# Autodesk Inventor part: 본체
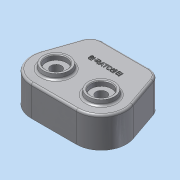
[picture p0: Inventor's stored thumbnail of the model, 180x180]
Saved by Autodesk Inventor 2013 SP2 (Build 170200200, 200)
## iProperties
Created: 2014-12
Part Number: 본체
Material: 알루미늄 6061
Document SubType Name: Modeling
Designer: dgall
Density: 2.71 g/cm^3
Mass: 613.441 g
Surface Area: 665.08 cm^2
Volume: 226.362 cm^3
Author: dgall
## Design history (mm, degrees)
sketch "스케치1"
  geometry: L1 (-47, 36)-(47, 36); L2 (47, 36)-(66.565, -20.803); L3 (32.527, -68.527)-(-32.527, -68.527); L4 (-66.565, -20.803)-(-47, 36); L5 (0, 0)-(-56.889, -56.889); L6 (0, 0)-(56.889, -56.889); L7 (0, 0)-(0, -80.453); L8 (61.837, -22.432)-(43.434, 31); L9 (43.434, 31)-(-43.434, 31); L10 (-43.434, 31)-(-61.837, -22.432); L11 (-32.527, -63.527)-(32.527, -63.527); C1 r 24 at (0, 0); C2 r 24 at (-32.527, -32.527); C3 r 24 at (32.527, -32.527); A1 r 36 centre (-32.527, -32.527) between (-66.565, -20.803) and (-32.527, -68.527); A2 r 36 centre (32.527, -32.527) between (32.527, -68.527) and (66.565, -20.803); A3 r 31 centre (-32.527, -32.527) between (-61.837, -22.432) and (-32.527, -63.527); A4 r 31 centre (32.527, -32.527) between (32.527, -63.527) and (61.837, -22.432); A5 r 46 centre (0, 0) between (-32.527, -32.527) and (32.527, -32.527); 2 further points
  constraints: 22 end point, 10 point on circle, 8 centre point, 4 coincident, 3 equal radius, 3 tangent, 2 equal length, 2 parallel, 2 point on line, 1 horizontal, 1 midpoint, 1 perpendicular, 1 vertical alignment, 5 other
  dimensions: "d2" = 48 diameter of C1; "d4" = 36 distance from line of L5.start L1; "d5" = 94 distance of L1.start L1.end; "d6" = 90 deg angle of L5 L6; "d7" = 45 deg angle of L7 L6; "d13" = 36 radius of A1; "d14" = 5 distance between parallel lines of L10 L4; "d26" = 46 radius of A5
extrude "돌출1" new body sketch "스케치1" distance "d15" = 44; taper "d16" = 0 deg
extrude "돌출2" cut sketch "스케치1" distance "d17" = 34; taper "d18" = 0 deg
sketch "스케치2"
  geometry: C1 r 24 at (0, 0); C2 r 24 at (-32.527, -32.527); C3 r 24 at (32.527, -32.527); A1 r 31 centre (-32.527, -32.527) between (-61.837, -22.432) and (-32.527, -63.527) reference; A2 r 31 centre (32.527, -32.527) between (32.527, -63.527) and (61.837, -22.432) reference; 1 further point
  constraints: 3 centre point, 3 coincident, 2 equal radius
  dimensions: "d19" = 48 diameter of C1
extrude "돌출3" join sketch "스케치2" distance "d21" = 11; taper "d22" = 0 deg
sketch "스케치3"
  geometry: C1 r 24 at (0, 0) reference; C2 r 20 at (0, 0); C3 r 10 at (0, 0)
  constraints: 2 centre point
  dimensions: "d23" = 40 diameter of C2; "d25" = 20 diameter of C3
extrude "돌출4" cut sketch "스케치3" distance "d27" = 12; taper "d28" = 0 deg
extrude "돌출5" cut sketch "스케치3" distance "d29" = 15; taper "d30" = 0 deg
sketch "스케치4"
  geometry: C1 r 20 at (-32.527, -32.527); C2 r 20 at (32.527, -32.527); A1 r 36 centre (-32.527, -32.527) between (-66.565, -20.803) and (-32.527, -68.527) reference; A2 r 36 centre (32.527, -32.527) between (32.527, -68.527) and (66.565, -20.803) reference; 1 further point
  constraints: 2 centre point, 2 coincident, 1 equal radius
  dimensions: "d31" = 40 diameter of C1
extrude "돌출6" join sketch "스케치4" distance "d33" = 7; taper "d34" = -10 deg
node "작업 평면1"
sketch "스케치5"
  geometry: L1 (-18.766, 51)-(18.766, 51) reference; L2 (-24, 23)-(24, 23) reference; L3 (41.054, 23)-(89.054, 23) reference; L4 (46.288, 51)-(83.82, 51) reference; L5 (0, 51)-(0, 23); L6 (65.054, 51)-(65.054, 23); L7 (0, 51)-(-15, 51); L8 (-15, 51)-(-15, 44); L9 (-15, 44)-(-7.75, 44); L10 (-7.75, 44)-(-7.75, 34); L11 (-7.75, 34)-(-17.5, 34); L12 (-17.5, 34)-(-17.5, 23); L13 (-17.5, 23)-(0, 23); L14 (65.054, 51)-(50.054, 51); L15 (50.054, 51)-(50.054, 44); L16 (50.054, 44)-(57.304, 44); L17 (57.304, 44)-(57.304, 34); L18 (57.304, 34)-(47.554, 34); L19 (47.554, 34)-(47.554, 23); L20 (47.554, 23)-(65.054, 23); 5 further points
  constraints: 32 end point, 7 perpendicular, 4 midpoint, 4 point on line, 3 parallel, 1 collinear, 1 horizontal
  dimensions: "d36" = 7 distance of L7.end L8.end; "d38" = 10 distance of L9.end L10.end; "d39" = 30 diameter of L8 L5; "d40" = 15.5 diameter of L10 L5; "d41" = 35 diameter of L12 L5; "d42" = 7 distance of L14.end L15.end; "d43" = 10 distance of L16.end L17.end; "d44" = 30 diameter of L15 L6; "d45" = 15.5 diameter of L17 L6; "d46" = 35 diameter of L19 L6
revolve "회전1" stored, may be unused: angle "d47" = 90 deg
revolve "회전2" stored, may be unused: angle "d48" = 90 deg
fillet "모깎기1" dims "d49" = 18
sketch "스케치6"
  geometry: L1 (34.162, 36)-(-34.162, 36) reference; L2 (-61.837, -22.432)-(-43.434, 31) reference; L3 (43.434, 31)-(61.837, -22.432) reference; L4 (32.527, -63.527)-(-32.527, -63.527) reference; A1 r 8 centre (-51.7, 7) between (-54.305, -0.564) and (-49.095, 14.564); A2 r 8 centre (51.7, 7) between (49.095, 14.564) and (54.305, -0.564); A3 r 8 centre (0, -63.527) between (8, -63.527) and (-8, -63.527); 1 further point
  constraints: 8 point on line, 6 point on circle, 3 centre point, 2 equal radius, 1 midpoint
  dimensions: "d50" = 8 radius of A1; "d52" = 29 distance from line of A1.centre L1; "d53" = 29 distance from line of A2.centre L1
extrude "돌출7" join sketch "스케치6" stored distance "d54" = 7; taper "d55" = 0 deg
fillet "모깎기2" dims "d56" = 13
fillet "모깎기3" dims "d57" = 3
hole "구멍1" diameter "d60" = 4.134; stored, may be unused: countersink angle "d64" = 90 deg, drill point angle "d66" = 118 deg; dims "d58" = 10, "d59" = 10, "d61" = 20, "d62" = 4, "d63" = 2, "d65" = 23
hole "구멍2" diameter "d69" = 4.134; stored, may be unused: countersink angle "d73" = 90 deg, drill point angle "d75" = 118 deg; dims "d67" = 10, "d68" = 10, "d70" = 20, "d71" = 4, "d72" = 2, "d74" = 23
hole "구멍3" diameter "d78" = 4.134; stored, may be unused: countersink angle "d82" = 90 deg, drill point angle "d84" = 118 deg; dims "d76" = 10, "d77" = 10, "d79" = 20, "d80" = 4, "d81" = 2, "d83" = 23
fillet "모깎기4" dims "d85" = 3
fillet "모깎기5" dims "d86" = 3
fillet "모깎기6" dims "d87" = 3
fillet "모깎기7" dims "d88" = 0.3
chamfer "모따기1" distance "d89" = 1; stored, may be unused: second distance "d90" = 2, angle "d91" = 45 deg
fillet "모깎기8" dims "d92" = 0.1
fillet "모깎기9" dims "d93" = 3
sketch "스케치7"
  geometry: L1 (34.162, 36)-(-34.162, 36) reference; 2 further points
  constraints: 1 vertical alignment, 1 other
  dimensions: "d94" = 30 distance from line of point (0, 6) L1
feature "엠보싱1" sketch "스케치7" dims "d2" = 48, "d4" = 36, "d5" = 94, "d6" = 90 deg, "d7" = 45 deg, "d13" = 36, "d14" = 5, "d18" = 0, "d26" = 46, "d95" = 1, "d96" = 0
fillet "모깎기10" dims "d97" = 3
fillet "모깎기11" dims "d98" = 3
node "솔리드1"
other parameters: "d12" = 36, "d35" = -36
